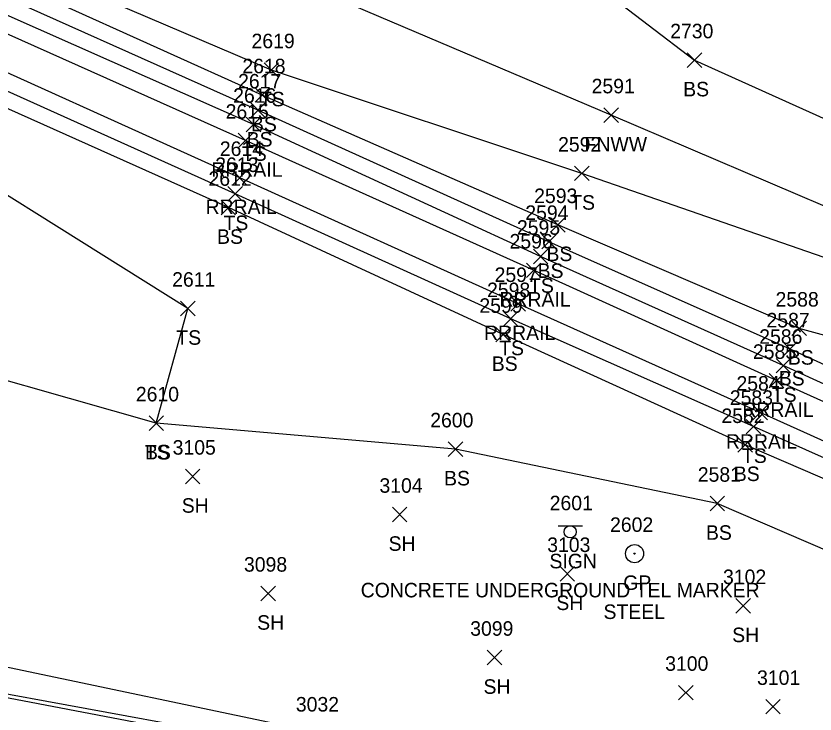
# Model space of a CAD drawing. Extents: x 1599569 to 1610055, y 642560 to 647860.
# Drawn here: x 1601023.2 to 1601133.3, y 647301.4 to 647397.5 of the extents above; entities that cross this region are included whole.
import ezdxf

# ---------------------------------------------------------------- set-up
doc = ezdxf.new("R2010")
doc.units = 0
for name, color, linetype in [('L_A', 7, 'Continuous'), ('L_I', 7, 'Continuous'), ('L_TIC', 7, 'Continuous'), ('LELB', 7, 'Continuous'), ('LFNC', 7, 'Continuous'), ('PET', 7, 'Continuous'), ('R_A', 7, 'Continuous'), ('R_C', 7, 'Continuous'), ('R_I', 7, 'Continuous'), ('R_TIC', 7, 'Continuous'), ('RGP', 7, 'Continuous'), ('RGR', 7, 'Continuous'), ('RR', 7, 'Continuous'), ('S_A', 7, 'Continuous'), ('S_C', 7, 'Continuous'), ('S_I', 7, 'Continuous'), ('SSGN', 7, 'Continuous')]:
    doc.layers.add(name, color=color, linetype=linetype)

msp = doc.modelspace()

# ---------------------------------------------------------------- linework, layer by layer
at = {"layer": 'L_TIC'}
for points in [[(1601115.74, 647390.45), (1601117.74, 647392.45)], [(1601117.74, 647390.45), (1601115.74, 647392.45)], [(1601057.43, 647389.08), (1601059.43, 647391.08)], [(1601059.43, 647389.08), (1601057.43, 647391.08)], [(1601056.17, 647385.63), (1601058.17, 647387.63)], [(1601058.17, 647385.63), (1601056.17, 647387.63)], [(1601055.58, 647383.54), (1601057.58, 647385.54)], [(1601057.58, 647383.54), (1601055.58, 647385.54)], [(1601104.25, 647382.87), (1601106.25, 647384.87)], [(1601106.25, 647382.87), (1601104.25, 647384.87)], [(1601054.96, 647381.57), (1601056.96, 647383.57)], [(1601056.96, 647381.57), (1601054.96, 647383.57)], [(1601100.2, 647374.84), (1601102.2, 647376.84)], [(1601102.2, 647374.84), (1601100.2, 647376.84)], [(1601052.43, 647372.03), (1601054.43, 647374.03)], [(1601054.43, 647372.03), (1601052.43, 647374.03)], [(1601051.5, 647370.13), (1601053.5, 647372.13)], [(1601053.5, 647370.13), (1601051.5, 647372.13)], [(1601096.9, 647367.75), (1601098.9, 647369.75)], [(1601098.9, 647367.75), (1601096.9, 647369.75)], [(1601095.68, 647365.43), (1601097.68, 647367.43)], [(1601097.68, 647365.43), (1601095.68, 647367.43)], [(1601094.53, 647363.39), (1601096.53, 647365.39)], [(1601096.53, 647363.39), (1601094.53, 647365.39)], [(1601045.92, 647356.23), (1601047.92, 647358.23)], [(1601047.92, 647356.23), (1601045.92, 647358.23)], [(1601090.41, 647354.79), (1601092.41, 647356.79)], [(1601092.41, 647354.79), (1601090.41, 647356.79)], [(1601089.36, 647352.63), (1601091.36, 647354.63)], [(1601091.36, 647352.63), (1601089.36, 647354.63)], [(1601130.17, 647353.49), (1601132.17, 647355.49)], [(1601132.17, 647353.49), (1601130.17, 647355.49)], [(1601128.91, 647350.62), (1601130.91, 647352.62)], [(1601130.91, 647350.62), (1601128.91, 647352.62)], [(1601127.98, 647348.36), (1601129.98, 647350.36)], [(1601129.98, 647348.36), (1601127.98, 647350.36)], [(1601041.57, 647340.43), (1601043.57, 647342.43)], [(1601043.57, 647340.43), (1601041.57, 647342.43)], [(1601041.57, 647340.43), (1601043.57, 647342.43)], [(1601043.57, 647340.43), (1601041.57, 647342.43)], [(1601123.87, 647339.95), (1601125.87, 647341.95)], [(1601125.87, 647339.95), (1601123.87, 647341.95)], [(1601122.71, 647337.45), (1601124.71, 647339.45)], [(1601124.71, 647337.45), (1601122.71, 647339.45)], [(1601082.79, 647336.85), (1601084.79, 647338.85)], [(1601084.79, 647336.85), (1601082.79, 647338.85)], [(1601046.59, 647333.09), (1601048.59, 647335.09)], [(1601048.59, 647333.09), (1601046.59, 647335.09)], [(1601118.88, 647329.36), (1601120.88, 647331.36)], [(1601120.88, 647329.36), (1601118.88, 647331.36)], [(1601075.1, 647327.84), (1601077.1, 647329.84)], [(1601077.1, 647327.84), (1601075.1, 647329.84)], [(1601098.21, 647319.68), (1601100.21, 647321.68)], [(1601100.21, 647319.68), (1601098.21, 647321.68)], [(1601056.99, 647316.97), (1601058.99, 647318.97)], [(1601058.99, 647316.97), (1601056.99, 647318.97)], [(1601122.44, 647315.26), (1601124.44, 647317.26)], [(1601124.44, 647315.26), (1601122.44, 647317.26)], [(1601088.17, 647308.14), (1601090.17, 647310.14)], [(1601090.17, 647308.14), (1601088.17, 647310.14)], [(1601114.55, 647303.31), (1601116.55, 647305.31)], [(1601116.55, 647303.31), (1601114.55, 647305.31)], [(1601126.56, 647301.37), (1601128.56, 647303.37)], [(1601128.56, 647301.37), (1601126.56, 647303.37)]]:
    msp.add_lwpolyline(points, dxfattribs=at)
at = {"layer": 'LELB'}
for points in [[(1601065.14, 647298.7), (1601017.93, 647308.63), (1600970.12, 647319.08), (1600922.99, 647332.86), (1600876.04, 647347.67), (1600828.44, 647364.9), (1600781.51, 647382.96), (1600734.1, 647401.33), (1600686.53, 647420.21), (1600637.49, 647439.52), (1600589.75, 647457.41), (1600542.23, 647476.94), (1600495.72, 647495.2), (1600449.86, 647513.12), (1600405.19, 647531.59), (1600383.83, 647541.02), (1600357.09, 647550.14)], [(1601042.57, 647341.43), (1601046.92, 647357.23), (1601002.18, 647385.23), (1600956.28, 647405.31), (1600905.33, 647430.67), (1600858.96, 647452.27), (1600808.26, 647474.67), (1600756.41, 647498.48), (1600709.6, 647519.51), (1600666.09, 647538.44)], [(1601329.86, 647260.18), (1601292.61, 647278.06), (1601262.72, 647292.4), (1601226.59, 647308.21), (1601190.68, 647323.36), (1601158.75, 647338.43), (1601129.91, 647351.62), (1601096.68, 647366.43), (1601056.58, 647384.54), (1601012.74, 647404.18), (1600965.22, 647426.07), (1600914.49, 647448.77), (1600866.79, 647471.13), (1600821.34, 647492.23), (1600763.72, 647518.52)], [(1601329.08, 647258.95), (1601292.39, 647275.61), (1601261.46, 647289.71), (1601225.27, 647305.87), (1601190.14, 647321.67), (1601157.62, 647336.35), (1601128.98, 647349.36), (1601095.53, 647364.39), (1601055.96, 647382.57), (1601011.7, 647402.22), (1600964.35, 647423.93), (1600913.28, 647446.74), (1600865.78, 647468.67), (1600819.14, 647488.99), (1600762.95, 647515.26)], [(1601326.17, 647250.65), (1601291.06, 647266.1), (1601257.88, 647281.25), (1601220.45, 647296.99), (1601187.26, 647312.94), (1601153.32, 647328.3), (1601124.87, 647340.95), (1601091.41, 647355.79), (1601053.43, 647373.03), (1601007.18, 647393.84), (1600960.43, 647415.03), (1600909.23, 647438.57), (1600861.95, 647459.92), (1600814.78, 647480.92), (1600758.97, 647506.06)], [(1601324.87, 647247.72), (1601290.33, 647262.4), (1601257.07, 647278.05), (1601219.4, 647295.14), (1601185.88, 647311.18), (1601152.37, 647326.07), (1601123.71, 647338.45), (1601090.36, 647353.63), (1601052.5, 647371.13), (1601006, 647391.96), (1600959.19, 647412.11), (1600907.65, 647435.58), (1600860.78, 647455.97), (1600813.3, 647477.78), (1600757.71, 647501.96)], [(1601277.64, 647306.94), (1601247.91, 647313.96), (1601233.47, 647321.04), (1601196.65, 647335.07), (1601162.36, 647345.97), (1601131.17, 647354.49), (1601097.9, 647368.75), (1601057.17, 647386.63), (1601013.7, 647406.22), (1600966.1, 647427.78), (1600916.08, 647451.44), (1600867.43, 647472.68), (1600824.54, 647496.94)], [(1601163.89, 647358.89), (1601162.92, 647352.78), (1601136.88, 647363.46), (1601101.2, 647375.84), (1601058.43, 647390.08), (1601014.73, 647408.69), (1600966.71, 647430.59), (1600917.74, 647454.04), (1600870.28, 647476.33), (1600824.54, 647496.94)], [(1600923.02, 647485.83), (1600958.02, 647473.82), (1601000.93, 647451.94), (1601046.02, 647433.27), (1601084.8, 647415.84), (1601116.74, 647391.45), (1601157.19, 647373.2)], [(1601172.91, 647224.25), (1601169.13, 647256.56), (1601171.19, 647281.1), (1601162.02, 647309.53), (1601148.33, 647318.11), (1601119.88, 647330.36), (1601083.79, 647337.85), (1601042.57, 647341.43), (1601006.37, 647351.71), (1600962.47, 647358.64), (1600928.59, 647369.58)]]:
    msp.add_lwpolyline(points, dxfattribs=at)
at = {"layer": 'LFNC'}
msp.add_lwpolyline([(1601438.38, 647230.38), (1601406.08, 647246.23), (1601390.36, 647253.65), (1601325.07, 647284.52), (1601295.93, 647298.24), (1601277.64, 647306.94), (1601251.54, 647319.32), (1601236.24, 647326.06), (1601200.38, 647343.03), (1601163.89, 647358.89), (1601138.18, 647369.81), (1601105.25, 647383.87), (1601061.33, 647402.55), (1601021.95, 647420.15), (1600970.86, 647443.1), (1600923.39, 647465.04), (1600876.08, 647486.37)], dxfattribs=at)
at = {"layer": 'PET'}
msp.add_lwpolyline([(1600771.17, 647353.24), (1600818.96, 647335.1), (1600868.96, 647317.44), (1600918.45, 647301.9), (1600965.93, 647288.14), (1601012.14, 647276.68), (1601059.75, 647265.92), (1601101.08, 647258.32), (1601112.42, 647256.46), (1601117.73, 647255.74), (1601120.06, 647270.86), (1601122, 647285.29), (1601116.76, 647286.06), (1601112.23, 647286.55), (1601065, 647295.38), (1601017.12, 647304.5), (1600969.14, 647315.57), (1600921.7, 647329.31), (1600875.33, 647343.78), (1600827.68, 647360.8), (1600779.98, 647378.97)], dxfattribs=at)
at = {"layer": 'R_TIC'}
for points in [[(1601053.86, 647379.37), (1601055.86, 647381.37)], [(1601055.86, 647379.37), (1601053.86, 647381.37)], [(1601053.06, 647374.24), (1601055.06, 647376.24)], [(1601055.06, 647374.24), (1601053.06, 647376.24)], [(1601093.57, 647361.49), (1601095.57, 647363.49)], [(1601095.57, 647361.49), (1601093.57, 647363.49)], [(1601091.45, 647356.88), (1601093.45, 647358.88)], [(1601093.45, 647356.88), (1601091.45, 647358.88)], [(1601127.05, 647346.29), (1601129.05, 647348.29)], [(1601129.05, 647346.29), (1601127.05, 647348.29)], [(1601124.78, 647341.91), (1601126.78, 647343.91)], [(1601126.78, 647341.91), (1601124.78, 647343.91)]]:
    msp.add_lwpolyline(points, dxfattribs=at)
at = {"layer": 'RGP'}
msp.add_line((1601108.48, 647323.45), (1601108.48, 647323.45), dxfattribs=at)
for radius in [1.25, 0.0833]:
    msp.add_circle((1601108.48, 647323.45), radius, dxfattribs=at)
at = {"layer": 'RGR'}
msp.add_lwpolyline([(1601112.7, 647287.9), (1601065.04, 647296.19), (1601016.91, 647305.01), (1600969.35, 647316.03), (1600921.82, 647329.78), (1600875.51, 647344.39), (1600827.81, 647361.39), (1600780.14, 647379.57), (1600733.34, 647397.57), (1600685.04, 647416.17), (1600636.13, 647435.4), (1600589.04, 647454.23), (1600540.52, 647473.18), (1600494.45, 647491.58), (1600448.44, 647509.99), (1600404.22, 647528.66), (1600382.85, 647539.14)], dxfattribs=at)
at = {"layer": 'RR'}
for points in [[(1601328.26, 647256.93), (1601292.48, 647273.14), (1601260.65, 647287.58), (1601223.96, 647303.96), (1601189.34, 647319.67), (1601156.57, 647334.47), (1601128.05, 647347.29), (1601094.57, 647362.49), (1601054.86, 647380.37), (1601010.55, 647400.2), (1600963.24, 647421.51), (1600912.09, 647444.53), (1600864.46, 647466.02), (1600817.98, 647486.96), (1600761.67, 647512.45)], [(1601326.5, 647252.29), (1601291.28, 647268.22), (1601258.56, 647283.04), (1601221.6, 647299.6), (1601187.65, 647314.96), (1601154.54, 647329.95), (1601125.78, 647342.91), (1601092.45, 647357.88), (1601054.06, 647375.24), (1601008.5, 647395.78), (1600961.24, 647417), (1600909.88, 647440.14), (1600862.44, 647461.47), (1600815.63, 647482.59), (1600759.94, 647507.87)]]:
    msp.add_lwpolyline(points, dxfattribs=at)
at = {"layer": 'SSGN'}
for p, q in [((1601097.97, 647327.29), (1601101.3, 647327.29)), ((1601099.61, 647326.45), (1601099.61, 647326.45))]:
    msp.add_line(p, q, dxfattribs=at)
msp.add_circle((1601099.61, 647326.45), 0.833, dxfattribs=at)

# ---------------------------------------------------------------- texts
at = {"layer": 'L_A'}
for s, p in [('BS', (1601115.18, 647386.45)), ('TS', (1601056.84, 647385.08)), ('BS', (1601055.61, 647381.63)), ('BS', (1601055.02, 647379.54)), ('FNWW', (1601101.59, 647378.87)), ('TS', (1601054.37, 647377.57)), ('TS', (1601099.61, 647370.84)), ('TS', (1601051.83, 647368.03)), ('BS', (1601050.94, 647366.13)), ('BS', (1601096.34, 647363.75)), ('BS', (1601095.12, 647361.43)), ('TS', (1601093.94, 647359.39)), ('TS', (1601045.33, 647352.23)), ('TS', (1601089.82, 647350.79)), ('BS', (1601129.61, 647349.49)), ('BS', (1601088.8, 647348.63)), ('BS', (1601128.36, 647346.62)), ('TS', (1601127.39, 647344.36)), ('TS', (1601040.98, 647336.43)), ('BS', (1601041.01, 647336.43)), ('TS', (1601123.28, 647335.95)), ('BS', (1601082.23, 647332.85)), ('BS', (1601122.16, 647333.45)), ('SH', (1601046.08, 647329.09)), ('BS', (1601118.32, 647325.36)), ('SH', (1601074.58, 647323.84)), ('SH', (1601097.7, 647315.68)), ('SH', (1601056.47, 647312.97)), ('SH', (1601121.93, 647311.26)), ('SH', (1601087.66, 647304.14))]:
    msp.add_text(s, height=2, dxfattribs=at).set_placement(p)
at = {"layer": 'L_I'}
for s, p in [('2730', (1601113.39, 647394.45)), ('2619', (1601055.69, 647393.08)), ('2618', (1601054.43, 647389.63)), ('2617', (1601053.84, 647387.54)), ('2591', (1601102.56, 647386.87)), ('2616', (1601053.16, 647385.57)), ('2592', (1601097.94, 647378.84)), ('2613', (1601050.69, 647376.03)), ('2612', (1601049.76, 647374.13)), ('2593', (1601094.64, 647371.75)), ('2594', (1601093.42, 647369.43)), ('2595', (1601092.27, 647367.39)), ('2611', (1601044.75, 647360.23)), ('2598', (1601088.15, 647358.79)), ('2588', (1601127.91, 647357.49)), ('2599', (1601087.09, 647356.63)), ('2587', (1601126.66, 647354.62)), ('2586', (1601125.66, 647352.36)), ('2610', (1601039.75, 647344.43)), ('2610', (1601039.75, 647344.43)), ('2583', (1601121.61, 647343.95)), ('2600', (1601080.32, 647340.85)), ('2582', (1601120.45, 647341.45)), ('3105', (1601044.82, 647337.09)), ('2581', (1601117.19, 647333.36)), ('3104', (1601073.32, 647331.84)), ('3103', (1601096.44, 647323.68)), ('3098', (1601054.65, 647320.97)), ('3102', (1601120.67, 647319.26)), ('3099', (1601085.83, 647312.14)), ('3100', (1601112.7, 647307.31)), ('3101', (1601125.36, 647305.37)), ('3032', (1601061.8, 647301.7)), ('3032', (1601061.8, 647301.7))]:
    msp.add_text(s, height=2, dxfattribs=at).set_placement(p)
at = {"layer": 'R_A'}
for s, p in [('RRRAIL', (1601050.15, 647375.37)), ('RRRAIL', (1601049.36, 647370.24)), ('RRRAIL', (1601089.86, 647357.49)), ('RRRAIL', (1601087.74, 647352.88)), ('RRRAIL', (1601123.34, 647342.29)), ('RRRAIL', (1601121.07, 647337.91)), ('GP', (1601106.92, 647318.45))]:
    msp.add_text(s, height=2, dxfattribs=at).set_placement(p)
at = {"layer": 'R_C'}
msp.add_text('STEEL', height=2, dxfattribs=at).set_placement((1601104.2, 647314.45))
at = {"layer": 'R_I'}
for s, p in [('2615', (1601052.12, 647383.37)), ('2614', (1601051.32, 647378.24)), ('2596', (1601091.25, 647365.49)), ('2597', (1601089.19, 647360.88)), ('2585', (1601124.79, 647350.29)), ('2584', (1601122.52, 647345.91)), ('2602', (1601105.1, 647326.45))]:
    msp.add_text(s, height=2, dxfattribs=at).set_placement(p)
at = {"layer": 'S_A'}
msp.add_text('SIGN', height=2, dxfattribs=at).set_placement((1601096.75, 647321.43))
at = {"layer": 'S_C'}
msp.add_text('CONCRETE UNDERGROUND TEL MARKER', height=2, dxfattribs=at).set_placement((1601070.74, 647317.43))
at = {"layer": 'S_I'}
msp.add_text('2601', height=2, dxfattribs=at).set_placement((1601096.78, 647329.43))

doc.saveas('drawing.dxf')
